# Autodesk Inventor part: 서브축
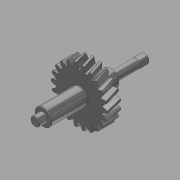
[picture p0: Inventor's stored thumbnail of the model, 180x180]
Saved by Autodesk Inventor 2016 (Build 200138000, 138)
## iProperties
Created: 2017-11
Part Number: 서브축
Material: 강철, 탄소
Document SubType Name: Modeling
Designer: mduedu
Categories: <?xml version="1.0" encoding="UTF-16"?> <MemberInstance><Categories><FamilyTemplate><FamilyTemplateParameter ValueType="xs:double" Id="1" ObjectReferenceKey="da
Density: 7.87 g/cm^3
Appearance: 반광택
Mass: 233.4 g
Surface Area: 98.1276 cm^2
Volume: 29.657 cm^3
CustomPartVersion: 1
Author: mduedu
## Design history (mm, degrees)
sketch "Sketch1"
  geometry: C1 r 24.776 at (0, 0)
  constraints: 1 centre point
  dimensions: "d0" = 49.55215 diameter of C1 (= da_da)
extrude "Extrusion1" new body sketch "Sketch1" distance "d1" = 12 (= da_b); taper "d2" = 0 deg
workplane "Work Plane2"
sketch "Sketch2"
  geometry: C1 r 24.776 at (0, 0) reference; C2 r 22.776 at (0, 0)
  constraints: 1 centre point, 1 coincident
  dimensions: "d3" = 45.55215 diameter of C2 (= da_dw)
feature "피치 지름" sketch "Sketch2" dims "d4" = 10, "d5" = 0
workplane "Work Plane8"
workplane "Work Plane9"
feature "스퍼 기어" dims "d34" = 1.428 (computed from da_z), "da_b" = 12, "da_d" = 45.55215, "da_aw" = 54.86964, "da_da" = 49.55215, "da_df" = 40.55215, "da_dw" = 45.55215, angle "da_beta" = 15 deg, "da_lefttooth" = 10, "da_righttooth" = 0
sketch "스케치3"
  geometry: C1 r 7.5 at (0, 0); 1 further point
  constraints: 1 centre point, 1 coincident
  dimensions: "d49" = 15 diameter of C1
extrude "돌출2" join sketch "스케치3" distance "d50" = 32; taper "d51" = 0 deg
sketch "스케치4"
  geometry: C1 r 4 at (0, 0); 1 further point
  constraints: 1 centre point, 1 coincident
  dimensions: "d52" = 8 diameter of C1
extrude "돌출3" join sketch "스케치4" distance "d53" = 7; taper "d54" = 0 deg
sketch "스케치5"
  geometry: C1 r 7.5 at (0, 0); 1 further point
  constraints: 1 centre point, 1 coincident
  dimensions: "d55" = 15 diameter of C1
extrude "돌출4" join sketch "스케치5" distance "d56" = 16; taper "d57" = 0 deg
sketch "스케치6"
  geometry: C1 r 4 at (0, 0); 1 further point
  constraints: 1 centre point, 1 coincident
  dimensions: "d58" = 8 diameter of C1
extrude "돌출5" join sketch "스케치6" distance "d59" = 30; taper "d60" = 0 deg
chamfer "모따기1" distance "d61" = 0.5; stored, may be unused: second distance "d62" = 2, angle "d63" = 45 deg
fillet "모깎기1" dims "d64" = 0.5
sketch "스케치7"
  geometry: L1 (-3.25, -3.25)-(3.25, -3.25); L2 (3.25, -3.25)-(3.25, 3.25); L3 (3.25, 3.25)-(-3.25, 3.25); L4 (-3.25, 3.25)-(-3.25, -3.25); L5 (-3.25, -3.25)-(3.25, 3.25); L6 (3.25, -3.25)-(-3.25, 3.25); L7 (-5, -5)-(5, -5); L8 (5, -5)-(5, 5); L9 (5, 5)-(-5, 5); L10 (-5, 5)-(-5, -5); L11 (-5, -5)-(5, 5); L12 (5, -5)-(-5, 5); 1 further point
  constraints: 24 end point, 4 midpoint, 4 parallel, 2 horizontal, 2 perpendicular
  dimensions: "d65" = 6.5 distance of L3.end L2.end; "d66" = 6.5 distance of L2.end L1.end; "d67" = 10 distance of L9.end L8.end; "d68" = 10 distance of L8.end L7.end
extrude "돌출6" cut sketch "스케치7" distance "d69" = 8; taper "d70" = 0 deg
body "Solid1"
body "Srf1"
other parameters: "d16" = 54.86964 (= da_aw), "d17" = 0, "d39" = 0, "d41" = 0, "d43" = 54.86964 (= da_aw), "d46" = 54.86964 (= da_aw), "d47" = 0, "d48" = 0
